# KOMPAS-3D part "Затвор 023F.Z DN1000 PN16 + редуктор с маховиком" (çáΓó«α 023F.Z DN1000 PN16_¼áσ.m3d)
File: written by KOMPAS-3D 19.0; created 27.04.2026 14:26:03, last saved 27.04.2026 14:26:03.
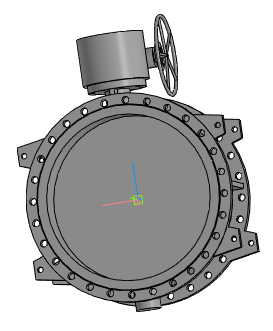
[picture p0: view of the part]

Document properties: Полное имя файла: ..\..\Затвор 023F.Z DN200-DN1600_с маховиком\Затвор 023F.Z DN1000 PN16 + редуктор с маховиком.a3d

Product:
- Part/product: Затвор 023F.Z DN1000 PN16 + редуктор с маховиком
    Масса: 1599.51

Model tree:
1. Операция без истории:1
